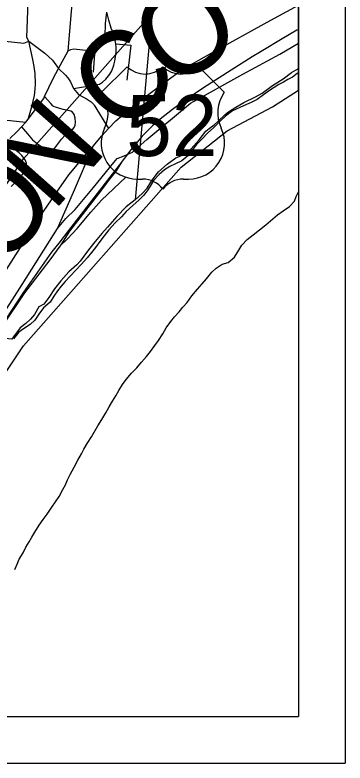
# Model space of a CAD drawing. Extents: x -8.2 to 38.5, y -0.1 to 21.9.
# Drawn here: x 8.353 to 9.063, y 13.864 to 15.475 of the extents above; entities that cross this region are included whole.
import ezdxf

# ---------------------------------------------------------------- set-up
doc = ezdxf.new("R2010")
doc.units = 0
for name, color, linetype in [('Default', 7, 'Continuous'), ('GM_X_Adjacent_County_Text', 7, 'Continuous'), ('GM_X_Airport_Location_Class_3', 7, 'Continuous'), ('GM_X_Section', 7, 'Continuous'), ('GM_X_Township', 7, 'Continuous'), ('GM_X_Township_Road_Text', 7, 'Continuous'), ('GM_X_Township_ROW', 7, 'Continuous'), ('GM_X_Township_Subdivision', 7, 'Continuous'), ('GM_X_Township_Subdivision_Text', 7, 'Continuous'), ('GM_X_Township_Text', 7, 'Continuous'), ('GM_X_Unincorporated_Location', 7, 'Continuous'), ('GM_X_US_Location', 7, 'Continuous')]:
    doc.layers.add(name, color=color, linetype=linetype)

msp = doc.modelspace()

# ---------------------------------------------------------------- linework, layer by layer
at = {"layer": 'Default'}
for points in [[(3.4133, 14.3673), (4.8235, 14.3673), (4.826, 14.3701), (4.9209, 14.4247), (5.0093, 14.4526), (5.1079, 14.4647), (5.3056, 14.4632), (5.5006, 14.42), (5.5963, 14.3828), (5.6234, 14.3673), (7.7858, 14.3673), (7.8175, 14.393), (7.9342, 14.5067), (8.01, 14.5807), (8.079, 14.6766), (8.1908, 14.868), (8.2378, 14.965), (8.3715, 15.1656), (8.4492, 15.2533), (8.7111, 15.5504), (8.81, 15.6288), (8.9073, 15.6804), (8.9634, 15.7165), (8.9634, 21.1673)], [(5.659, 13.9645), (7.7815, 13.9645), (7.785, 13.9675), (7.8175, 13.9901), (7.9343, 14.104), (7.9435, 14.1129), (8.01, 14.1778), (8.079, 14.2737), (8.1908, 14.4651), (8.2378, 14.5622), (8.3715, 14.7627), (8.7111, 15.1475), (8.81, 15.226), (8.9073, 15.2775), (8.9634, 15.3136), (8.9634, 20.7535)], [(8.6736, 15.7659), (8.6117, 15.0774), (8.6272, 15.091), (8.6377, 15.1026), (8.6459, 15.1153), (8.6483, 15.1198), (8.6619, 15.1373), (8.6808, 15.1543), (8.6997, 15.1675), (8.7176, 15.1751), (8.7242, 15.1799), (8.7323, 15.1873), (8.7494, 15.2062), (8.7638, 15.2248), (8.7715, 15.2307), (8.7819, 15.2385), (8.79, 15.2459), (8.8062, 15.2618), (8.8124, 15.2666), (8.8282, 15.2769), (8.8454, 15.2871), (8.8707, 15.2991), (8.8852, 15.3071), (8.9076, 15.3233), (8.9306, 15.3375), (8.9483, 15.3512), (8.9634, 15.3597), (8.9634, 15.7309)]]:
    msp.add_lwpolyline(points, dxfattribs=at)
at = {"layer": 'GM_X_Adjacent_County_Text'}
msp.add_lwpolyline([(7.66, 15.8712), (8.6736, 15.7659), (8.6117, 15.0774), (8.5928, 15.0619), (8.5723, 15.0415), (8.5525, 15.0184), (8.5405, 15.0046), (8.5226, 14.9831), (8.5094, 14.9667), (8.4937, 14.9454), (8.4864, 14.9373), (8.469, 14.9221), (8.4519, 14.9028), (8.4387, 14.8852), (8.4261, 14.8666), (8.4156, 14.8524), (8.4049, 14.847), (8.3954, 14.8305), (8.3869, 14.8201), (8.3765, 14.8112), (8.3645, 14.8016), (8.3536, 14.7875), (8.3469, 14.777), (7.5202, 14.8634)], close=True, dxfattribs=at)
at = {"layer": 'GM_X_Airport_Location_Class_3'}
for points in [[(8.522, 15.193), (8.5404, 15.2147), (8.5543, 15.231), (8.5701, 15.2472), (8.5988, 15.2717), (8.6192, 15.288), (8.672, 15.3277), (8.6964, 15.3457), (8.7163, 15.3593), (8.7821, 15.3965), (8.8958, 15.4595), (8.9634, 15.4962)], [(8.2868, 14.7665), (8.2975, 14.7835), (8.3686, 14.8951), (8.4453, 15.0151), (8.4629, 15.0371), (8.4831, 15.0564), (8.5226, 15.1034), (8.5659, 15.1575), (8.5734, 15.1663), (8.5885, 15.1717), (8.6066, 15.1801), (8.637, 15.2073), (8.7309, 15.2851), (8.7549, 15.2981), (8.8434, 15.3476), (8.923, 15.391), (8.9634, 15.4145)], [(8.2727, 14.8257), (8.2852, 14.8458), (8.3214, 14.9055), (8.3454, 14.9429), (8.3821, 15.0002), (8.415, 15.0522), (8.4475, 15.1001), (8.4691, 15.1308), (8.5096, 15.1789), (8.522, 15.193)]]:
    msp.add_lwpolyline(points, dxfattribs=at)
at = {"layer": 'GM_X_Section'}
msp.add_lwpolyline([(5.659, 13.9645), (7.7815, 13.9645), (7.785, 13.9675), (7.8175, 13.9901), (7.9343, 14.104), (7.9435, 14.1129), (8.01, 14.1778), (8.079, 14.2737), (8.1908, 14.4651), (8.2378, 14.5622), (8.3715, 14.7627), (8.7111, 15.1475), (8.81, 15.226), (8.9073, 15.2775), (8.9634, 15.3136), (8.9634, 20.7645)], dxfattribs=at)
at = {"layer": 'GM_X_Township'}
for p, q in [((9.0634, 20.8645), (9.0634, 13.8645)), ((8.9634, 20.7645), (8.9634, 13.9645)), ((2.1634, 13.9645), (8.9634, 13.9645)), ((2.0634, 13.8645), (9.0634, 13.8645))]:
    msp.add_line(p, q, dxfattribs=at)
at = {"layer": 'GM_X_Township_ROW'}
for points in [[(8.9634, 15.3505), (8.9606, 15.3492), (8.9502, 15.3415), (8.9403, 15.336), (8.9307, 15.3308), (8.9207, 15.3253), (8.9111, 15.3191), (8.9008, 15.3125), (8.8877, 15.3032), (8.8742, 15.2929), (8.8612, 15.287), (8.8517, 15.2827), (8.8372, 15.2761), (8.8211, 15.2685), (8.8061, 15.2574), (8.7961, 15.2477), (8.7806, 15.2325), (8.7683, 15.2213), (8.7551, 15.2075), (8.7439, 15.196), (8.733, 15.1825), (8.7256, 15.172), (8.7125, 15.1609), (8.6987, 15.1547), (8.6865, 15.1489), (8.6754, 15.1415), (8.6634, 15.1319), (8.6511, 15.1185), (8.6444, 15.1068), (8.6381, 15.0963), (8.6296, 15.0866), (8.6203, 15.0769), (8.6072, 15.065), (8.5925, 15.0524), (8.5824, 15.0405), (8.5689, 15.0275), (8.5557, 15.0125), (8.5456, 14.9998), (8.5359, 14.9875), (8.5266, 14.9747), (8.5184, 14.9639), (8.5087, 14.9523), (8.4967, 14.9389), (8.4723, 14.9128), (8.4615, 14.9012), (8.4529, 14.8912), (8.4448, 14.8811), (8.437, 14.8695), (8.4291, 14.8571), (8.4149, 14.8444), (8.4051, 14.831), (8.3961, 14.8179), (8.3861, 14.8089), (8.3715, 14.7994), (8.3615, 14.7923), (8.3503, 14.7778)], [(8.6619, 14.7745), (8.6716, 14.7887), (8.6787, 14.8015), (8.6888, 14.8154), (8.6966, 14.8255), (8.7063, 14.8359), (8.7148, 14.846), (8.7241, 14.8564), (8.7342, 14.8703), (8.7463, 14.8845), (8.756, 14.8961), (8.7657, 14.9073), (8.7766, 14.9211), (8.7862, 14.93), (8.7993, 14.9389), (8.8122, 14.9424), (8.8257, 14.9539), (8.8351, 14.9689), (8.8417, 14.9794), (8.8526, 14.9917), (8.8661, 15.0017), (8.8791, 15.0125), (8.8934, 15.0236), (8.908, 15.0366), (8.9181, 15.0447), (8.93, 15.0532), (8.9442, 15.0628), (8.955, 15.074), (8.9586, 15.0842), (8.9634, 15.0946)], [(8.3534, 14.2813), (8.3582, 14.2926), (8.3622, 14.3031), (8.3708, 14.317), (8.3768, 14.3294), (8.3842, 14.3407), (8.3901, 14.3508), (8.3963, 14.3617), (8.4057, 14.3767), (8.4139, 14.3887), (8.4225, 14.4003), (8.433, 14.4153), (8.4405, 14.4269), (8.4483, 14.4385), (8.4565, 14.4531), (8.462, 14.4637), (8.4664, 14.4742), (8.4723, 14.4859), (8.481, 14.5017), (8.4889, 14.5167), (8.4967, 14.5302), (8.5015, 14.5404), (8.5089, 14.5527), (8.5183, 14.5666), (8.532, 14.5903), (8.5403, 14.6045), (8.5489, 14.6188), (8.556, 14.6316), (8.5634, 14.6436), (8.5705, 14.6552), (8.5767, 14.6668), (8.5846, 14.6796), (8.5928, 14.6904), (8.6044, 14.7039), (8.6156, 14.7154), (8.6253, 14.7274), (8.6362, 14.7397), (8.6451, 14.7509), (8.6541, 14.7633), (8.6619, 14.7745)]]:
    msp.add_lwpolyline(points, dxfattribs=at)
at = {"layer": 'GM_X_Township_Subdivision'}
for p, q in [((8.5948, 15.3637), (8.5399, 15.3088)), ((8.8035, 15.3088), (8.7486, 15.3637)), ((8.6168, 15.122), (8.6278, 15.122)), ((8.7157, 15.122), (8.7266, 15.122))]:
    msp.add_line(p, q, dxfattribs=at)
for centre, radius, start, end in [((8.6333, 15.4029), 0.0549, 225.573, 314.427), ((8.7102, 15.4029), 0.0549, 225.573, 314.427), ((8.4769, 15.2647), 0.0769, 334.5471, 35.0009), ((8.8665, 15.2647), 0.0769, 144.9991, 205.4529), ((8.6159, 15.1989), 0.0769, 154.8319, 270.6383), ((8.7275, 15.1989), 0.0769, 269.3617, 25.1681), ((8.6278, 15.0671), 0.0549, 36.8699, 90), ((8.7157, 15.0671), 0.0549, 90, 143.1301)]:
    msp.add_arc(centre, radius, start, end, dxfattribs=at)
at = {"layer": 'GM_X_Township_Subdivision_Text'}
for p, q in [((8.5223, 15.3521), (8.5263, 15.4008)), ((8.5703, 15.4132), (8.6027, 15.41)), ((8.6027, 15.41), (8.5944, 15.3351)), ((8.3084, 15.2518), (8.3768, 15.2446))]:
    msp.add_line(p, q, dxfattribs=at)
for points in [[(8.4679, 15.3979), (8.4785, 15.5261), (8.4846, 15.5828), (8.4982, 15.7147), (8.5051, 15.779), (8.5146, 15.8851), (8.5274, 16.0001), (8.5297, 16.0531), (8.5406, 16.1469), (8.5513, 16.2228), (8.5561, 16.2582), (8.5566, 16.2671), (8.5554, 16.273)], [(8.383, 15.4188), (8.3787, 15.4267), (8.3822, 15.5025), (8.3853, 15.5328), (8.3867, 15.5464), (8.3941, 15.6184), (8.4078, 15.7227), (8.4082, 15.7252), (8.4122, 15.7477), (8.4162, 15.7891), (8.4265, 15.8917), (8.4379, 16.0065)], [(8.0753, 15.4486), (8.1269, 15.4394), (8.2035, 15.4317), (8.2649, 15.4255), (8.2849, 15.4235), (8.3722, 15.4142), (8.383, 15.4188)], [(8.3674, 15.2345), (8.3807, 15.2196), (8.3912, 15.2062), (8.4018, 15.1974), (8.4113, 15.1913), (8.4215, 15.185), (8.4295, 15.1842), (8.4338, 15.1855), (8.4391, 15.1883), (8.4429, 15.1938), (8.4451, 15.1961), (8.4533, 15.2081), (8.4617, 15.2163), (8.4706, 15.2249), (8.4786, 15.2301), (8.4803, 15.2322), (8.4826, 15.2372), (8.4834, 15.2444), (8.4828, 15.2528), (8.481, 15.2608), (8.4796, 15.2634), (8.477, 15.2658), (8.4737, 15.2679), (8.4706, 15.2689), (8.457, 15.2714), (8.4404, 15.277), (8.4371, 15.2779), (8.4361, 15.2783), (8.4347, 15.2794), (8.4303, 15.2844), (8.4168, 15.2994)], [(8.345, 15.1056), (8.3611, 15.1211), (8.3664, 15.1273), (8.3712, 15.1333), (8.3771, 15.1441), (8.3787, 15.1494), (8.3782, 15.1563), (8.3751, 15.1633), (8.3681, 15.1727), (8.3628, 15.1783), (8.3542, 15.1849), (8.333, 15.1954)], [(8.4453, 15.0151), (8.4797, 15.0937), (8.522, 15.193)]]:
    msp.add_lwpolyline(points, dxfattribs=at)
at = {"layer": 'GM_X_Township_Text'}
for points in [[(8.3427, 15.2089), (8.3572, 15.2238), (8.3674, 15.2345), (8.3768, 15.2446), (8.3822, 15.2508), (8.4153, 15.2956), (8.4168, 15.2994), (8.4358, 15.3381), (8.4473, 15.3598), (8.4679, 15.3979), (8.4736, 15.4012), (8.4803, 15.4021), (8.5062, 15.3991), (8.5136, 15.3985), (8.5217, 15.3997), (8.5263, 15.4008), (8.5309, 15.4032), (8.5347, 15.4057), (8.5386, 15.4089), (8.5429, 15.4138), (8.5454, 15.4197), (8.5472, 15.4295), (8.5481, 15.457), (8.5512, 15.4815)], [(8.4795, 15.3167), (8.5351, 15.3259), (8.542, 15.3304), (8.5492, 15.3369), (8.5573, 15.3478), (8.5617, 15.3552), (8.566, 15.3669), (8.5681, 15.3761), (8.5711, 15.395), (8.5713, 15.4045), (8.5703, 15.4132), (8.569, 15.4205), (8.5668, 15.4285), (8.5639, 15.4367), (8.5622, 15.4417), (8.5602, 15.4471), (8.5557, 15.4641), (8.5512, 15.4815)], [(8.3822, 15.2508), (8.3865, 15.2654), (8.3889, 15.2751), (8.3917, 15.2868), (8.3953, 15.3016), (8.397, 15.3157), (8.3978, 15.3271), (8.3972, 15.3489), (8.395, 15.3646), (8.3916, 15.3795), (8.383, 15.4188)], [(8.383, 15.4188), (8.3922, 15.4126), (8.4034, 15.4037), (8.4175, 15.3928), (8.434, 15.3779), (8.4473, 15.3598)], [(8.4473, 15.3598), (8.4623, 15.3458), (8.4673, 15.3402), (8.4729, 15.3314), (8.4795, 15.3167), (8.4902, 15.3041), (8.5086, 15.2942), (8.5172, 15.288), (8.5203, 15.2853), (8.5228, 15.2826), (8.5238, 15.2812), (8.5543, 15.231)]]:
    msp.add_lwpolyline(points, dxfattribs=at)
at = {"layer": 'GM_X_US_Location'}
for points in [[(8.9634, 15.4443), (8.9598, 15.4423), (8.928, 15.4235), (8.8828, 15.3967), (8.8634, 15.3848), (8.8182, 15.3566), (8.759, 15.318), (8.7169, 15.2894), (8.6921, 15.2714), (8.6656, 15.2506), (8.6496, 15.2365), (8.6383, 15.2256), (8.6271, 15.214), (8.6163, 15.2015), (8.603, 15.1848), (8.5774, 15.1517), (8.5522, 15.1196), (8.5354, 15.0973), (8.4909, 15.0395), (8.4689, 15.0111), (8.4475, 14.9838), (8.4321, 14.9643), (8.372, 14.8782), (8.3208, 14.8018)], [(8.5828, 15.1586), (8.5711, 15.1397), (8.5542, 15.1181), (8.5373, 15.0958), (8.4928, 15.0381), (8.4708, 15.0096), (8.4518, 14.9802), (8.45, 14.9777)], [(8.45, 14.9777), (8.4664, 14.9934), (8.4876, 15.0158), (8.5167, 15.0503), (8.5395, 15.0768), (8.5922, 15.126)], [(8.45, 14.9777), (8.4286, 14.9482), (8.374, 14.8769), (8.3228, 14.8005), (8.2703, 14.7175), (8.191, 14.5872), (8.1512, 14.524), (8.1281, 14.4881), (8.1146, 14.4715)]]:
    msp.add_lwpolyline(points, dxfattribs=at)

# ---------------------------------------------------------------- texts
at = {"layer": 'GM_X_Township_Road_Text'}
for s, p in [('0', (8.6716, 15.2363)), ('/', (8.6717, 15.2363))]:
    msp.add_text(s, height=0.000189, dxfattribs=at).set_placement(p)
msp.add_text('52', height=0.000189, rotation=0, dxfattribs=at).set_placement((8.6325, 15.1971))
at = {"layer": 'GM_X_Township_Subdivision'}
msp.add_text('52', height=0.13184, dxfattribs=at).set_placement((8.5929, 15.1714))
at = {"layer": 'GM_X_Unincorporated_Location'}
for s, rotation, p in [('O', 33.3739, (8.6888, 15.3112)), ('C', 42.2889, (8.5809, 15.2123)), ('N', 48.41, (8.4345, 15.0485)), ('O', 48.7572, (8.3243, 14.9228))]:
    msp.add_text(s, height=0.1894, rotation=rotation, dxfattribs=at).set_placement(p)

doc.saveas('drawing.dxf')
